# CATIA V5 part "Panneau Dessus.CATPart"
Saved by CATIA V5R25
Part number: Panneau Dessus
Bounding box of the stored display mesh (mm): x -160 to 160, y -55 to 55, z 0 to 3
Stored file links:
  C:\Users\m000605\Desktop\Projet FAB liseuse\Panneau Dessus.CATPart
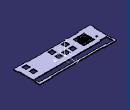
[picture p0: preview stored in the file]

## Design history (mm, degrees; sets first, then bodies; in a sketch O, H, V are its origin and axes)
AxisSystem1: origin (0, 0, 0), X (1, 0, 0), Y (0, 1, 0), Z (0, 0, 1)
Set1
  Sketch1 on XY plane of AxisSystem1, origin (0, 0, 0), H (1, 0, 0), V (0, 1, 0)
    line L1 (-107, 55) -> (-107, 52)
    line L2 (-107, 52) -> (107, 52)
    line L3 (107, 52) -> (107, 55)
    line L4 (107, 55) -> (160, 55)
    line L5 (160, 55) -> (160, 35)
    line L6 (160, 35) -> (157, 35)
    line L7 (157, 35) -> (157, -35)
    line L8 (160, -35) -> (157, -35)
    line L9 (160, -35) -> (160, -55)
    line L10 (160, -55) -> (107, -55)
    point P11 (107, -55)
    line L11 (107, -55) -> (107, -52)
    line L12 (107, -52) -> (-107, -52)
    point P13 (-107, -52)
    line L13 (-107, -52) -> (-107, -55)
    point P14 (-107, -55)
    line L14 (-107, -55) -> (-160, -55)
    line L15 (-160, -55) -> (-160, -35)
    point P16 (-160, -35)
    line L16 (-160, -35) -> (-157, -35)
    line L17 (-157, -35) -> (-157, 35)
    point P18 (-157, 35)
    line L18 (-157, 35) -> (-160, 35)
    point P19 (-160, 35)
    line L19 (-160, 35) -> (-160, 55)
    point P20 (-160, 55)
    line L20 (-160, 55) -> (-107, 55)
    reference intersected line E1 through (0, 0) direction (0, 1) from YZ plane of AxisSystem1
    reference projected line E2 through (0, 0) direction (1, 0) from edge [XY plane of AxisSystem1 | ZX plane of AxisSystem1]
    reference intersected line E3 through (0, 0) direction (0, 1) from YZ plane of AxisSystem1
    reference intersected line E4 through (0, 0) direction (0, 1) from YZ plane of AxisSystem1
    reference intersected line E5 through (0, 0) direction (-1, 0) from ZX plane of AxisSystem1
    reference projected line E6 through (0, 0) direction (0, 1) from edge [YZ plane of AxisSystem1 | XY plane of AxisSystem1]
    distance L19 L5 = 320
    distance L10 L4 = 110
    distance L7 L5 = 3
    distance L2 L4 = 3
    distance L16 L18 = 70
    distance L3 L5 = 53
    vertical: L1 V, L3 V, L5 V, L7 V, L9 V, L11 V, L13 V, L15 V, L17 V, L19 V
    horizontal: L2 H, L4 H, L6 H, L8 H, L10 H, L12 H, L14 H, L16 H, L18 H, L20 H
    coincidence: P11 L3, P13 L1, P14 L10, P16 L8, P18 L6, P19 L15, P20 L4
    symmetry: L17 L7 E1, L12 L2 H, L4 L10 H, L14 L20 E2, L19 L5 E3, L15 L9 E4, L16 L18 E5, L1 L3 E6
Body1 (main body)
  Pad1: profile Sketch1, direction (0, 0, 1), length 3
  Sketch2 on end face of Pad1, origin (0, 0, 3), H (1, 0, 0), V (0, 1, 0)
    line L1 (-19, 3) -> (-1, 3)
    line L2 (-1, 3) -> (-1, -15)
    line L3 (-1, -15) -> (-19, -15)
    line L4 (-19, -15) -> (-19, 3)
    reference projected line E1 (-160, -55) -> (-107, -55) from edge [face of Pad1 from Sketch1.L14 | end face of Pad1]
    reference projected line E2 (-160, -35) -> (-160, -55) from edge [face of Pad1 from Sketch1.L15 | end face of Pad1]
    point P5 (9, 3)
    line L5 (9, 3) -> (27, 3)
    line L6 (27, 3) -> (27, -15)
    line L7 (27, -15) -> (9, -15)
    line L8 (9, -15) -> (9, 3)
    point P7 (27, -15)
    point P9 (9, -27)
    line L9 (9, -27) -> (27, -27)
    line L10 (27, -27) -> (27, -45)
    line L11 (27, -45) -> (9, -45)
    line L12 (9, -45) -> (9, -27)
    point P11 (27, -45)
    point P13 (-29, 3)
    line L13 (-29, 3) -> (-47, 3)
    line L14 (-47, 3) -> (-47, -15)
    line L15 (-47, -15) -> (-29, -15)
    line L16 (-29, -15) -> (-29, 3)
    point P15 (-47, -15)
    point P17 (-29, -27)
    line L17 (-29, -27) -> (-47, -27)
    line L18 (-47, -27) -> (-47, -45)
    line L19 (-47, -45) -> (-29, -45)
    line L20 (-29, -45) -> (-29, -27)
    point P19 (-47, -45)
    reference projected line E3 (107, -55) -> (160, -55) from edge [face of Pad1 from Sketch1.L10 | end face of Pad1]
    reference projected line E4 (-160, -55) -> (-107, -55) from edge [face of Pad1 from Sketch1.L14 | end face of Pad1]
    point P21 (117, 3)
    line L21 (117, 3) -> (135, 3)
    line L22 (135, 3) -> (135, -15)
    line L23 (135, -15) -> (117, -15)
    line L24 (117, -15) -> (117, 3)
    point P23 (135, -15)
    point P25 (117, -27)
    line L25 (117, -27) -> (135, -27)
    line L26 (135, -27) -> (135, -45)
    line L27 (135, -45) -> (117, -45)
    line L28 (117, -45) -> (117, -27)
    point P27 (135, -45)
    reference projected line E5 (160, -55) -> (160, -35) from edge [face of Pad1 from Sketch1.L9 | end face of Pad1]
    circle A1 centre (-132, 0) radius 3
    reference projected line E6 (-160, -35) -> (-160, -55) from edge [face of Pad1 from Sketch1.L15 | end face of Pad1]
    line L29 (153, 45) -> (-125, 45)
    line L30 (-125, 25) -> (153, 25)
    line L31 (153, 25) -> (153, 45)
    reference projected line E7 (160, 35) -> (160, 55) from edge [face of Pad1 from Sketch1.L5 | end face of Pad1]
    reference projected line E8 (160, 55) -> (107, 55) from edge [face of Pad1 from Sketch1.L4 | end face of Pad1]
    line L32 (-152, 49) -> (-125, 49)
    line L33 (-125, 49) -> (-125, 45)
    line L34 (-125, 21) -> (-152, 21)
    point P36 (-125, 25)
    line L35 (-125, 25) -> (-125, 21)
    line L36 (-152, 21) -> (-152, 49)
    reference projected line E9 (-160, 55) -> (-160, 35) from edge [face of Pad1 from Sketch1.L19 | end face of Pad1]
    length L2 = 18
    distance E1 L3 = 40
    distance E2 L4 = 141
    distance L4 L2 = 18
    distance L11 E3 = 10
    distance L19 E4 = 10
    length L18 = 18
    length L12 = 18
    distance L2 L8 = 10
    length L5 = 18
    distance L16 L4 = 10
    length L13 = 18
    distance L24 L22 = 18
    distance L22 E5 = 25
    radius A1 = 3
    distance A1 E6 = 25
    distance L31 E7 = 7
    distance L29 E8 = 10
    distance L30 L29 = 20
    length L33 = 4
    length L35 = 4
    distance L31 L36 = 305
    distance L33 E9 = 35
    horizontal: L1 H, L3 H, L5 H, L7 H, L9 H, L11 H, L13 H, L15 H, L17 H, L19 H, L21 H, L23 H, L25 H, L27 H, L29 H, L30 H, L32 H, L34 H
    vertical: L2 V, L4 V, L6 V, L8 V, L10 V, L12 V, L14 V, L16 V, L18 V, L20 V, L22 V, L24 V, L26 V, L28 V, L31 V, L33 V, L35 V, L36 V
    coincidence: P5 L1, P7 L3, P9 L8, P11 L6, P13 L1, P15 L3, P17 L16, P19 L14, P21 L1, P23 L3, P25 L24, P25 L9, P27 L22, P27 L11, L33 P36, L33 L35
    tangency: A1 L1
  Pocket1: profile Sketch2, direction (0, 0, -1), length 3
  Sketch3 on end face of Pad1, origin (0, 0, 3), H (1, 0, 0), V (0, 1, 0)
    circle A1 centre (-116, 7) radius 1
    reference projected line E1 (-125, 25) -> (153, 25) from edge [end face of Pad1 | face of Pocket1 from Sketch2.L30]
    reference projected line E2 (-157, 35) -> (-157, -35) from edge [face of Pad1 from Sketch1.L17 | end face of Pad1]
    radius A1 = 1
    distance A1 E1 = 17
    distance A1 E2 = 42
  Pocket2: profile Sketch3, direction (0, 0, -1), length 3
  RectPattern1: of Pocket2, direction 1 instances 12, spacing 4, along end face of Pad1, direction 2 instances 12, spacing -4, along end face of Pad1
